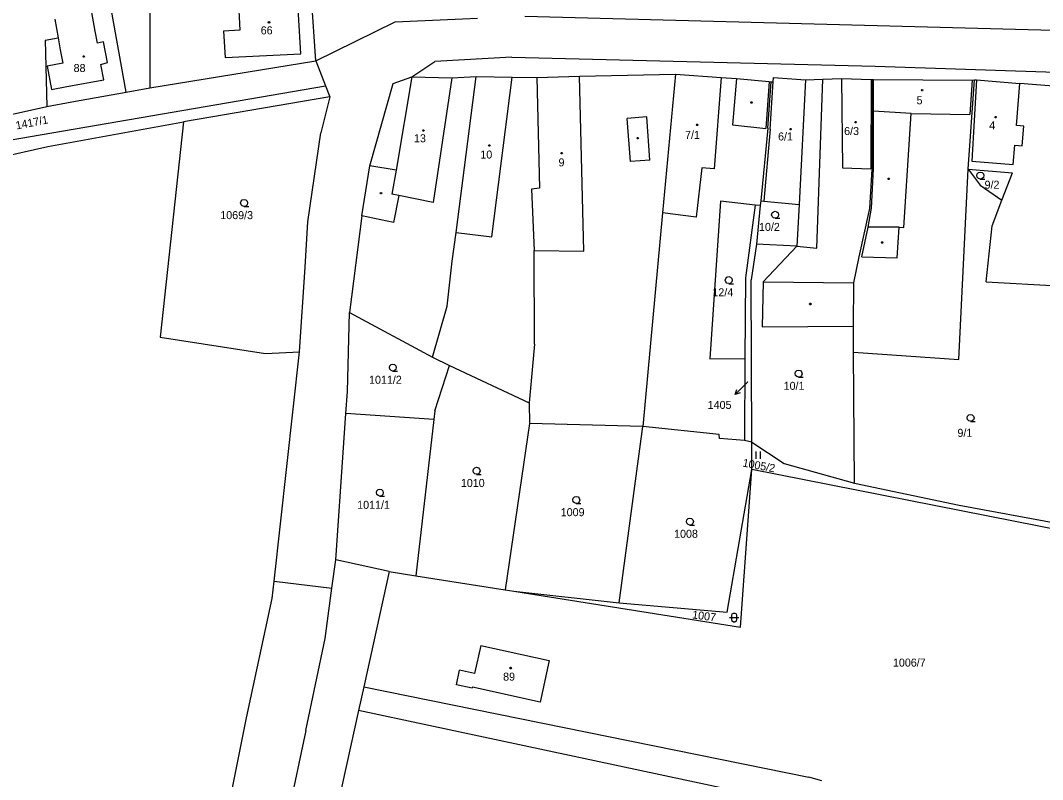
# Model space of a CAD drawing. Extents: x -852001 to -842497, y -1063614 to -1052182.
# Drawn here: x -849639.2 to -849422.1, y -1056500 to -1056338.8 of the extents above; entities that cross this region are included whole.
import ezdxf

# ---------------------------------------------------------------- set-up
doc = ezdxf.new("R2010")
doc.units = 0
for name, color, linetype in [('Default', 7, 'Continuous'), ('KN_HRANICE', 7, 'Continuous'), ('KN_KULTURY', 7, 'Continuous'), ('KN_PARCELY', 7, 'Continuous'), ('KN_SLUCKY', 7, 'Continuous')]:
    doc.layers.add(name, color=color, linetype=linetype)

# ---------------------------------------------------------------- blocks, each defined once
blk = doc.blocks.new('304')
at = {"layer": 'Default'}
blk.add_lwpolyline([(0, 0), (-0.38, 0.1), (-0.65, 0.37), (-0.75, 0.74), (-0.65, 1.11), (-0.38, 1.38), (-0.01, 1.48), (0.36, 1.38), (0.63, 1.11), (0.73, 0.73), (0.63, 0.35), (0.36, 0.08), (-0.02, -0.02), (0.98, -0.02)], dxfattribs=at)
blk = doc.blocks.new('306')
at = {"layer": 'Default'}
for p, q in [((-0.5, 1.5), (-0.5, 0)), ((0.5, 0), (0.5, 1.5))]:
    blk.add_line(p, q, dxfattribs=at)
blk = doc.blocks.new('316')
at = {"layer": 'Default'}
for points in [[(-1, 1), (0.27, 1), (1, 1)], [(-0.5, 1.5), (-0.4, 1.79), (-0.15, 1.97), (0.16, 1.97), (0.41, 1.79), (0.51, 1.5), (0.51, 0.5), (0.41, 0.21), (0.16, 0.03), (-0.15, 0.03), (-0.4, 0.21), (-0.5, 0.5), (-0.5, 1.5)]]:
    blk.add_lwpolyline(points, dxfattribs=at)
blk = doc.blocks.new('10292')
at = {"layer": 'Default'}
blk.add_line((0, 3), (0, 0), dxfattribs=at)
blk.add_lwpolyline([(-0.5, 2), (0, 3), (0.5, 2)], dxfattribs=at)
blk = doc.blocks.new('402')
at = {"layer": 'Default'}
blk.add_lwpolyline([(0.09, 0.15), (0.18, 0), (0.09, -0.15), (-0.09, -0.15), (-0.18, 0), (-0.09, 0.15), (0.09, 0.15)], dxfattribs=at)

msp = doc.modelspace()

# ---------------------------------------------------------------- linework, layer by layer
at = {"layer": 'KN_HRANICE'}
for p, q in [((-849576.45, -1056347.39), (-849578.15, -1056322.42)), ((-849616.72, -1056354), (-849620.5, -1056332.96)), ((-849611.73, -1056334.13), (-849611.68, -1056353.09)), ((-849406.11, -1056341.28), (-849532.06, -1056337.93)), ((-849631.91, -1056338.54), (-849631.2, -1056342.49)), ((-849576.45, -1056347.39), (-849559.57, -1056339.1)), ((-849559.57, -1056339.1), (-849542.14, -1056338.3)), ((-849633.92, -1056342.98), (-849631.2, -1056342.49)), ((-849633.92, -1056342.98), (-849633.57, -1056357.04)), ((-849534.81, -1056346.62), (-849551.16, -1056347.5)), ((-849534.81, -1056346.62), (-849457.69, -1056348.54)), ((-849611.68, -1056353.09), (-849576.45, -1056347.39)), ((-849576.45, -1056347.39), (-849574.4, -1056352.7)), ((-849556.04, -1056350.8), (-849551.16, -1056347.5)), ((-849457.69, -1056348.54), (-849398.2, -1056350.42)), ((-849560.02, -1056352.2), (-849556.04, -1056350.8)), ((-849556.04, -1056350.8), (-849547.59, -1056351.01)), ((-849547.59, -1056351.01), (-849542.41, -1056350.72)), ((-849546.62, -1056383.82), (-849542.41, -1056350.72)), ((-849542.41, -1056350.72), (-849534.78, -1056350.83)), ((-849534.78, -1056350.83), (-849529.54, -1056350.88)), ((-849529.54, -1056350.88), (-849520.48, -1056350.65)), ((-849529.54, -1056350.88), (-849528.97, -1056374.41)), ((-849520.48, -1056350.65), (-849500.05, -1056350.21)), ((-849500.05, -1056350.21), (-849502.8, -1056379.68)), ((-849500.05, -1056350.21), (-849490.37, -1056350.9)), ((-849490.37, -1056350.9), (-849487.09, -1056351.14)), ((-849487.09, -1056351.14), (-849480.14, -1056351.77)), ((-849479.29, -1056351.85), (-849479.23, -1056350.91)), ((-849479.23, -1056350.91), (-849472.47, -1056351.4)), ((-849468.75, -1056351.27), (-849464.83, -1056351.13)), ((-849464.83, -1056351.13), (-849458.48, -1056351.34)), ((-849685.84, -1056371.84), (-849574.4, -1056352.7)), ((-849616.72, -1056354), (-849611.68, -1056353.09)), ((-849574.4, -1056352.7), (-849573.5, -1056355.04)), ((-849564.99, -1056369.69), (-849560.02, -1056352.2)), ((-849480.43, -1056361.68), (-849479.72, -1056351.81)), ((-849480.14, -1056351.77), (-849479.72, -1056351.81)), ((-849479.72, -1056351.81), (-849479.29, -1056351.85)), ((-849472.47, -1056351.4), (-849468.75, -1056351.27)), ((-849470.08, -1056387.16), (-849468.75, -1056351.27)), ((-849458.48, -1056351.34), (-849458.24, -1056351.35)), ((-849458.24, -1056351.35), (-849458.31, -1056370.39)), ((-849458.24, -1056351.35), (-849457.99, -1056351.31)), ((-849457.99, -1056351.31), (-849437.06, -1056351.45)), ((-849437.9, -1056370.41), (-849436.56, -1056351.44)), ((-849437.06, -1056351.45), (-849436.56, -1056351.44)), ((-849436.56, -1056351.44), (-849436.13, -1056351.44)), ((-849436.13, -1056351.44), (-849426.94, -1056352.2)), ((-849416.15, -1056353.07), (-849426.94, -1056352.2)), ((-849628.29, -1056356.09), (-849616.72, -1056354)), ((-849573.5, -1056355.04), (-849604.58, -1056360.3)), ((-849573.5, -1056355.04), (-849575.39, -1056362.66)), ((-849674.41, -1056366.2), (-849633.57, -1056357.04)), ((-849633.57, -1056357.04), (-849628.29, -1056356.09)), ((-849633.36, -1056365.59), (-849604.58, -1056360.3)), ((-849604.58, -1056360.3), (-849609.54, -1056406.05)), ((-849480.43, -1056361.68), (-849481.92, -1056377.09)), ((-849578.13, -1056381.59), (-849575.39, -1056362.66)), ((-849673.7, -1056374.66), (-849633.36, -1056365.59)), ((-849566.68, -1056380.28), (-849564.99, -1056369.69)), ((-849458.76, -1056378.72), (-849458.31, -1056370.39)), ((-849439.86, -1056410.77), (-849437.9, -1056370.41)), ((-849437.9, -1056370.41), (-849428.51, -1056371.18)), ((-849437.9, -1056370.41), (-849435.36, -1056373.81)), ((-849430.75, -1056376.96), (-849428.51, -1056371.18)), ((-849528.97, -1056374.41), (-849530.67, -1056374.61)), ((-849530.67, -1056374.61), (-849530.07, -1056387.67)), ((-849435.36, -1056373.81), (-849430.75, -1056376.96)), ((-849490.51, -1056377.17), (-849492.74, -1056410.69)), ((-849483.12, -1056378), (-849490.51, -1056377.17)), ((-849481.92, -1056377.09), (-849482.05, -1056378.12)), ((-849481.92, -1056377.09), (-849481.33, -1056377.15)), ((-849481.33, -1056377.15), (-849473.83, -1056377.89)), ((-849432.79, -1056382.39), (-849430.75, -1056376.96)), ((-849483.12, -1056378), (-849485.17, -1056393.49)), ((-849482.05, -1056378.12), (-849483.12, -1056378)), ((-849482.05, -1056378.12), (-849482.89, -1056386.33)), ((-849473.83, -1056377.89), (-849474.29, -1056386.75)), ((-849461.04, -1056389.01), (-849458.76, -1056378.72)), ((-849578.69, -1056391.21), (-849578.13, -1056381.59)), ((-849566.68, -1056380.28), (-849569.32, -1056400.81)), ((-849502.8, -1056379.68), (-849507.03, -1056425.02)), ((-849547.5, -1056389.93), (-849546.62, -1056383.82)), ((-849434.1, -1056394.27), (-849432.79, -1056382.39)), ((-849530, -1056407.52), (-849530.07, -1056387.67)), ((-849482.89, -1056386.33), (-849483.96, -1056393.89)), ((-849474.29, -1056386.75), (-849482.89, -1056386.33)), ((-849474.29, -1056386.75), (-849481.42, -1056394.34)), ((-849474.29, -1056386.75), (-849470.08, -1056387.16)), ((-849548.57, -1056399.5), (-849547.5, -1056389.93)), ((-849462.21, -1056394.54), (-849461.04, -1056389.01)), ((-849579.89, -1056409.19), (-849578.69, -1056391.21)), ((-849485.17, -1056393.49), (-849485.33, -1056410.62)), ((-849483.82, -1056428.39), (-849483.96, -1056393.89)), ((-849481.42, -1056394.34), (-849481.68, -1056403.84)), ((-849462.29, -1056403.7), (-849462.21, -1056394.54)), ((-849434.1, -1056394.27), (-849418.85, -1056395.14)), ((-849569.73, -1056417.59), (-849569.32, -1056400.81)), ((-849569.32, -1056400.81), (-849551.71, -1056410.33)), ((-849551.71, -1056410.33), (-849548.57, -1056399.5)), ((-849481.68, -1056403.84), (-849462.29, -1056403.7)), ((-849462.25, -1056409.27), (-849462.29, -1056403.7)), ((-849609.54, -1056406.05), (-849587.11, -1056409.52)), ((-849530, -1056407.52), (-849531.15, -1056419.97)), ((-849587.11, -1056409.52), (-849579.89, -1056409.19)), ((-849585.31, -1056457.89), (-849579.89, -1056409.19)), ((-849462.06, -1056437.04), (-849462.25, -1056409.27)), ((-849462.25, -1056409.27), (-849439.86, -1056410.77)), ((-849551.71, -1056410.33), (-849548.04, -1056412.05)), ((-849492.74, -1056410.69), (-849485.33, -1056410.62)), ((-849485.33, -1056410.62), (-849485.43, -1056428.03)), ((-849551.15, -1056421.68), (-849548.04, -1056412.05)), ((-849548.04, -1056412.05), (-849531.15, -1056419.97)), ((-849570.06, -1056422.29), (-849569.73, -1056417.59)), ((-849531.15, -1056419.97), (-849531.06, -1056424.37)), ((-849572.24, -1056453.32), (-849570.06, -1056422.29)), ((-849551.37, -1056423.56), (-849570.06, -1056422.29)), ((-849551.15, -1056421.68), (-849551.37, -1056423.56)), ((-849551.37, -1056423.56), (-849555.21, -1056456.71)), ((-849531.06, -1056424.37), (-849536.26, -1056459.7)), ((-849507.03, -1056425.02), (-849531.06, -1056424.37)), ((-849512.05, -1056462.5), (-849507.03, -1056425.02)), ((-849490.78, -1056426.73), (-849507.03, -1056425.02)), ((-849490.69, -1056427.59), (-849490.78, -1056426.73)), ((-849485.43, -1056428.03), (-849490.69, -1056427.59)), ((-849483.82, -1056428.39), (-849485.43, -1056428.03)), ((-849483.86, -1056434.18), (-849483.82, -1056428.39)), ((-849483.82, -1056428.39), (-849476.99, -1056432.86)), ((-849476.99, -1056432.86), (-849462.06, -1056437.04)), ((-849489.06, -1056464.49), (-849483.86, -1056434.18)), ((-849486.28, -1056467.61), (-849483.86, -1056434.18)), ((-849371.72, -1056456.31), (-849483.86, -1056434.18)), ((-849462.06, -1056437.04), (-849439.82, -1056441.73)), ((-849439.82, -1056441.73), (-849419.09, -1056445.59)), ((-849573.04, -1056459.35), (-849572.24, -1056453.32)), ((-849560.89, -1056455.81), (-849572.24, -1056453.32)), ((-849560.89, -1056455.81), (-849566.27, -1056480.31)), ((-849560.89, -1056455.81), (-849555.21, -1056456.71)), ((-849555.21, -1056456.71), (-849536.26, -1056459.7)), ((-849585.72, -1056461.57), (-849585.31, -1056457.89)), ((-849585.31, -1056457.89), (-849573.04, -1056459.35)), ((-849574.46, -1056470.04), (-849573.04, -1056459.35)), ((-849536.26, -1056459.7), (-849534.42, -1056460.02)), ((-849591.21, -1056486.93), (-849585.72, -1056461.57)), ((-849534.42, -1056460.02), (-849512.05, -1056462.5)), ((-849534.42, -1056460.02), (-849486.28, -1056467.61)), ((-849512.05, -1056462.5), (-849489.06, -1056464.49)), ((-849578.61, -1056489.59), (-849574.46, -1056470.04)), ((-849541.4, -1056471.57), (-849542.79, -1056477.49)), ((-849541.4, -1056471.57), (-849526.88, -1056474.69)), ((-849526.88, -1056474.69), (-849528.79, -1056483.54)), ((-849546.56, -1056479.92), (-849545.91, -1056476.77)), ((-849542.79, -1056477.49), (-849545.91, -1056476.77)), ((-849566.27, -1056480.31), (-849567.38, -1056485.36)), ((-849566.27, -1056480.31), (-849471.74, -1056499.48)), ((-849543.23, -1056480.62), (-849546.56, -1056479.92)), ((-849543.17, -1056480.41), (-849543.23, -1056480.62)), ((-849528.79, -1056483.54), (-849543.17, -1056480.41)), ((-849567.38, -1056485.36), (-849598.49, -1056626.95)), ((-849477.73, -1056504.47), (-849567.38, -1056485.36)), ((-849601.24, -1056537.2), (-849591.21, -1056486.93)), ((-849578.61, -1056489.59), (-849604.54, -1056611.95)), ((-849468.95, -1056500.27), (-849471.74, -1056499.48))]:
    msp.add_line(p, q, dxfattribs=at)
at = {"layer": 'KN_PARCELY'}
msp.add_line((-849484.68, -1056415.57), (-849485.24, -1056416.13), dxfattribs=at)
at = {"layer": 'KN_SLUCKY'}
for p, q in [((-849579.67, -1056345.88), (-849580.93, -1056322.58)), ((-849623.34, -1056341.09), (-849624.66, -1056333.71)), ((-849593.06, -1056332.62), (-849592.57, -1056340.88)), ((-849631.2, -1056342.49), (-849630.75, -1056345.04)), ((-849622.85, -1056343.61), (-849623.34, -1056341.09)), ((-849592.57, -1056340.88), (-849596.08, -1056341.09)), ((-849596.08, -1056341.09), (-849595.73, -1056346.69)), ((-849621.57, -1056343.36), (-849622.85, -1056343.61)), ((-849620.72, -1056347.73), (-849621.57, -1056343.36)), ((-849630.75, -1056345.04), (-849630.22, -1056347.9)), ((-849595.73, -1056346.69), (-849579.67, -1056345.88)), ((-849630.22, -1056347.9), (-849633.49, -1056348.51)), ((-849633.49, -1056348.51), (-849632.58, -1056353.43)), ((-849622.1, -1056348.13), (-849620.72, -1056347.73)), ((-849621.5, -1056351.43), (-849622.1, -1056348.13)), ((-849556.04, -1056350.8), (-849559.41, -1056370.58)), ((-849547.59, -1056351.01), (-849551.51, -1056377.44)), ((-849539.06, -1056384.74), (-849534.78, -1056350.83)), ((-849519.54, -1056387.79), (-849520.48, -1056350.65)), ((-849490.37, -1056350.9), (-849491.86, -1056370.31)), ((-849487.09, -1056351.14), (-849487.95, -1056360.98)), ((-849464.83, -1056351.13), (-849464.57, -1056370.11)), ((-849632.58, -1056353.43), (-849629.33, -1056352.84)), ((-849629.33, -1056352.84), (-849621.5, -1056351.43)), ((-849480.14, -1056351.77), (-849480.9, -1056361.73)), ((-849479.96, -1056361.85), (-849479.29, -1056351.85)), ((-849472.47, -1056351.4), (-849473.83, -1056377.89)), ((-849458.48, -1056351.34), (-849458.6, -1056370.29)), ((-849457.99, -1056358.05), (-849457.99, -1056351.31)), ((-849437.06, -1056351.45), (-849437.53, -1056358.8)), ((-849436.13, -1056351.44), (-849437.16, -1056368.68)), ((-849427.67, -1056361.1), (-849426.94, -1056352.2)), ((-849506.16, -1056359.3), (-849510.3, -1056359.6)), ((-849509.64, -1056368.77), (-849510.3, -1056359.6)), ((-849505.5, -1056368.48), (-849506.16, -1056359.3)), ((-849450.04, -1056358.54), (-849457.99, -1056358.05)), ((-849457.98, -1056370.31), (-849457.99, -1056358.05)), ((-849451.58, -1056382.74), (-849450.04, -1056358.54)), ((-849450.04, -1056358.54), (-849437.53, -1056358.8)), ((-849487.95, -1056360.98), (-849480.9, -1056361.73)), ((-849479.96, -1056361.85), (-849481.33, -1056377.15)), ((-849426.11, -1056361.23), (-849427.67, -1056361.1)), ((-849426.45, -1056365.39), (-849426.11, -1056361.23)), ((-849428.33, -1056369.36), (-849428.02, -1056365.27)), ((-849428.02, -1056365.27), (-849426.45, -1056365.39)), ((-849505.5, -1056368.48), (-849509.64, -1056368.77)), ((-849559.41, -1056370.58), (-849564.99, -1056369.69)), ((-849559.41, -1056370.58), (-849560.28, -1056375.69)), ((-849494.48, -1056370.13), (-849495.68, -1056380.57)), ((-849491.86, -1056370.31), (-849494.48, -1056370.13)), ((-849464.57, -1056370.11), (-849458.6, -1056370.29)), ((-849458.45, -1056378.68), (-849457.98, -1056370.31)), ((-849437.16, -1056368.68), (-849428.33, -1056369.36)), ((-849558.83, -1056375.98), (-849560.28, -1056375.69)), ((-849558.83, -1056375.98), (-849559.93, -1056381.74)), ((-849551.51, -1056377.44), (-849558.83, -1056375.98)), ((-849459.13, -1056382.68), (-849458.45, -1056378.68)), ((-849559.93, -1056381.74), (-849566.68, -1056380.28)), ((-849495.68, -1056380.57), (-849502.8, -1056379.68)), ((-849546.62, -1056383.82), (-849539.06, -1056384.74)), ((-849460.5, -1056389.02), (-849459.13, -1056382.68)), ((-849452.58, -1056382.72), (-849459.13, -1056382.68)), ((-849453, -1056389.21), (-849452.58, -1056382.72)), ((-849452.58, -1056382.72), (-849451.58, -1056382.74)), ((-849530.07, -1056387.67), (-849519.54, -1056387.79)), ((-849460.5, -1056389.02), (-849453, -1056389.21)), ((-849481.42, -1056394.34), (-849462.21, -1056394.54))]:
    msp.add_line(p, q, dxfattribs=at)

# ---------------------------------------------------------------- block references
at = {"layer": 'KN_KULTURY'}
for name, p in [('402', (-849586.39, -1056339.2)), ('402', (-849625.74, -1056346.44)), ('402', (-849447.68, -1056353.59)), ('402', (-849483.92, -1056356.22)), ('402', (-849432.09, -1056359.36)), ('402', (-849553.59, -1056362.16)), ('402', (-849495.46, -1056360.98)), ('402', (-849475.63, -1056361.88)), ('402', (-849461.83, -1056360.39)), ('402', (-849508.08, -1056363.77)), ('402', (-849539.6, -1056365.36)), ('402', (-849524.25, -1056366.97)), ('402', (-849454.79, -1056372.42)), ('304', (-849435.31, -1056372.47)), ('304', (-849591.69, -1056378.29)), ('402', (-849562.61, -1056375.5)), ('304', (-849478.89, -1056380.79)), ('402', (-849456.17, -1056385.97)), ('304', (-849488.75, -1056394.68)), ('402', (-849471.42, -1056399.02)), ('304', (-849560.09, -1056413.25)), ('304', (-849473.9, -1056414.54)), ('304', (-849437.38, -1056423.93)), ('306', (-849482.51, -1056431.87)), ('304', (-849542.29, -1056435.17)), ('304', (-849562.85, -1056439.81)), ('304', (-849521.12, -1056441.37)), ('304', (-849497, -1056445.96)), ('316', (-849487.62, -1056466.61)), ('402', (-849535.1, -1056476.31))]:
    msp.add_blockref(name, p, dxfattribs=at)
at = {"layer": 'KN_PARCELY', "rotation": 134.988857}
msp.add_blockref('10292', (-849485.24, -1056416.13), dxfattribs=at)

# ---------------------------------------------------------------- texts
at = {"layer": 'KN_PARCELY'}
for s, height, p in [('66', 1.7, (-849588.16, -1056341.75)), ('88', 1.7, (-849627.9, -1056349.75)), ('5', 1.7, (-849448.86, -1056356.6)), ('6/3', 1.7, (-849464.25, -1056363.13)), ('4', 1.7, (-849433.43, -1056361.92)), ('13', 1.7, (-849555.61, -1056364.67)), ('7/1', 1.7, (-849498.04, -1056363.94)), ('6/1', 1.7, (-849478.28, -1056364.28)), ('10', 1.7, (-849541.51, -1056368.12)), ('9', 1.7, (-849524.91, -1056369.79)), ('9/2', 1.7, (-849434.42, -1056374.53)), ('1069/3', 1.7, (-849596.75, -1056380.99)), ('10/2', 1.7, (-849482.33, -1056383.49)), ('12/4', 1.7, (-849492.23, -1056397.38)), ('1011/2', 1.7, (-849565.15, -1056415.95)), ('1405', 0.1, (-849484.88, -1056415.57)), ('10/1', 1.7, (-849477.1, -1056417.24)), ('1405', 1.7, (-849493.23, -1056421.29)), ('9/1', 1.7, (-849440.18, -1056427.22)), ('1010', 1.7, (-849545.65, -1056437.87)), ('1011/1', 1.7, (-849567.67, -1056442.51)), ('1009', 1.7, (-849524.44, -1056444.07)), ('1008', 1.7, (-849500.36, -1056448.66)), ('1006/7', 1.7, (-849453.88, -1056476.02)), ('89', 1.7, (-849536.68, -1056479.01))]:
    msp.add_text(s, height=height, dxfattribs=at).set_placement(p)
for s, rotation, p in [('1417/1', 10.886, (-849640.03, -1056361.96)), ('1005/2', 349.504, (-849485.91, -1056433.51)), ('1007', 352.426, (-849496.6, -1056465.77))]:
    msp.add_text(s, height=1.7, rotation=rotation, dxfattribs=at).set_placement(p)

doc.saveas('drawing.dxf')
